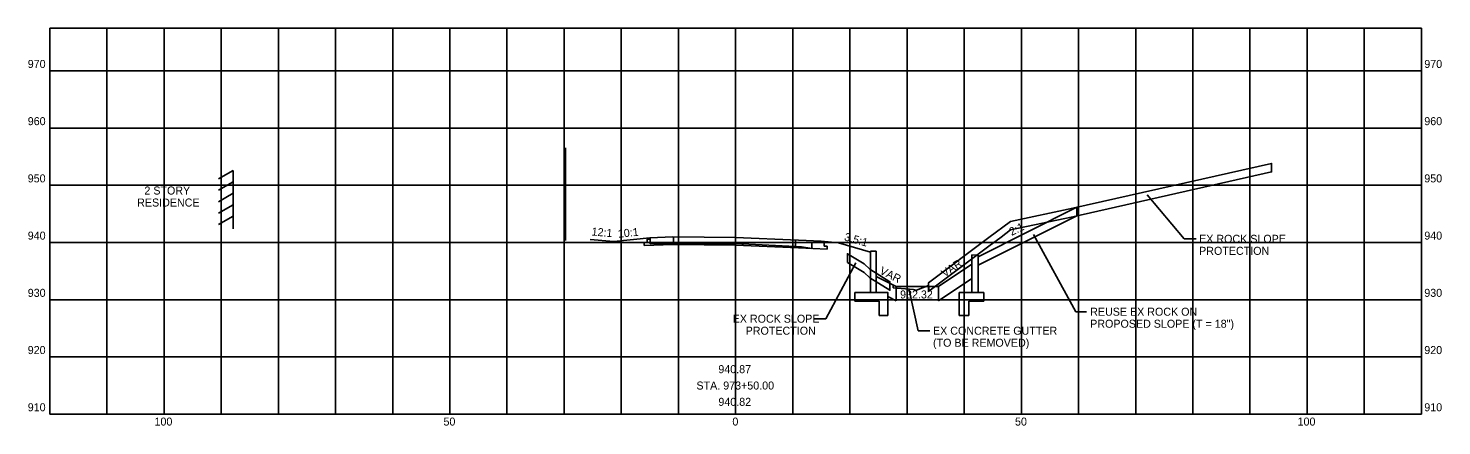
# Model space of a CAD drawing. Extents: x -124 to 124, y 908 to 977.
import ezdxf

# ---------------------------------------------------------------- set-up
doc = ezdxf.new("R2010")
doc.units = 0
for name, color, linetype in [('BD_X_Building', 7, 'Continuous'), ('GT_Project_Soil_Boring', 7, 'Continuous'), ('RD_X_Misc_Items', 7, 'Continuous'), ('SH_Major_Grid_Line', 7, 'Continuous'), ('SH_Text', 7, 'Continuous'), ('SN_X_Public', 7, 'Continuous'), ('SV_P_Aerial_Targets', 7, 'Continuous'), ('SV_X_Control_Cells_Found', 7, 'Continuous'), ('SV_X_Mon_Cells_Found', 7, 'Continuous'), ('SV_X_Random_Point', 7, 'Continuous'), ('UT_X_Gas_Cells', 7, 'Continuous'), ('UT_X_Sanitary_Cells', 7, 'Continuous'), ('UT_X_Water_Cells', 7, 'Continuous')]:
    doc.layers.add(name, color=color, linetype=linetype)

msp = doc.modelspace()

# ---------------------------------------------------------------- linework, layer by layer
at = {"layer": 'BD_X_Building'}
for p, q in [((59.73, 946.16), (42.45, 937.52)), ((59.73, 946.16), (59.73, 944.66)), ((59.73, 944.66), (42.45, 936.02)), ((35.52, 932.32), (41.34, 936.2)), ((28.07, 932.32), (24.62, 934.03)), ((35.52, 929.82), (41.34, 933.7)), ((28.07, 929.82), (26.62, 930.54)), ((28.07, 932.32), (28.07, 929.82)), ((35.52, 932.32), (35.52, 929.82))]:
    msp.add_line(p, q, dxfattribs=at)
for points in [[(42.45, 936.02), (59.73, 944.66), (59.73, 946.16), (42.45, 937.52), (42.45, 936.02)], [(35.52, 929.82), (41.34, 933.7), (41.34, 936.2), (35.52, 932.32), (35.52, 929.82)], [(28.07, 929.82), (28.07, 932.32), (24.62, 934.03), (24.62, 931.26), (26.62, 931.26), (26.62, 930.54)]]:
    msp.add_lwpolyline(points, close=True, dxfattribs=at)
at = {"layer": 'GT_Project_Soil_Boring'}
for p, q in [((-87.91, 952.6), (-90.49, 951.13)), ((-87.91, 942.37), (-87.91, 952.6)), ((-87.91, 950.6), (-90.49, 949.13)), ((-87.91, 948.6), (-90.49, 947.13)), ((-87.91, 946.6), (-90.49, 945.13)), ((-87.91, 944.6), (-90.49, 943.13))]:
    msp.add_line(p, q, dxfattribs=at)
at = {"layer": 'RD_X_Misc_Items'}
for p, q in [((-21.32, 940.2), (-25.46, 940.54)), ((-15, 940.83), (-21.32, 940.2)), ((15, 940.22), (18, 939.92)), ((18, 939.92), (23.62, 938.32)), ((28.07, 932.32), (35.52, 932.32))]:
    msp.add_line(p, q, dxfattribs=at)
at = {"layer": 'SH_Major_Grid_Line'}
for p, q in [((-120, 977.43), (120, 977.43)), ((-120, 910), (-120, 977.43)), ((-110, 910), (-110, 977.43)), ((-100, 910), (-100, 977.43)), ((-90, 910), (-90, 977.43)), ((-80, 910), (-80, 977.43)), ((-70, 910), (-70, 977.43)), ((-60, 910), (-60, 977.43)), ((-50, 910), (-50, 977.43)), ((-40, 910), (-40, 977.43)), ((-30, 910), (-30, 977.43)), ((-20, 910), (-20, 977.43)), ((-10, 910), (-10, 977.43)), ((0, 910), (0, 977.43)), ((10, 910), (10, 977.43)), ((20, 910), (20, 977.43)), ((30, 910), (30, 977.43)), ((40, 910), (40, 977.43)), ((50, 910), (50, 977.43)), ((60, 910), (60, 977.43)), ((70, 910), (70, 977.43)), ((80, 910), (80, 977.43)), ((90, 910), (90, 977.43)), ((100, 910), (100, 977.43)), ((110, 910), (110, 977.43)), ((120, 910), (120, 977.43)), ((-120, 970), (120, 970)), ((-120, 960), (120, 960)), ((-120, 950), (120, 950)), ((-120, 940), (120, 940)), ((-120, 930), (120, 930)), ((-120, 920), (120, 920)), ((-120, 910), (120, 910))]:
    msp.add_line(p, q, dxfattribs=at)
at = {"layer": 'SN_X_Public'}
for p, q in [((-14.96, 939.77), (-14.96, 940.77)), ((-10.89, 939.85), (-10.89, 940.85)), ((10.48, 939.3), (10.48, 940.3)), ((13.32, 938.95), (13.32, 939.95))]:
    msp.add_line(p, q, dxfattribs=at)
msp.add_lwpolyline([(-14.96, 939.77), (-12.52, 939.81), (-10.89, 939.85), (-8.36, 939.85), (-0.19, 939.83), (2.3, 939.71), (10.48, 939.3), (11.51, 939.22), (13.32, 938.95)], dxfattribs=at)
at = {"layer": 'SV_P_Aerial_Targets'}
for p, q in [((78.51, 940.64), (72.03, 948.35)), ((80.56, 940.64), (78.51, 940.64)), ((15.81, 926.68), (21.06, 936.43)), ((31.95, 924.58), (30.32, 931.95)), ((13.76, 926.68), (15.81, 926.68)), ((33.99, 924.58), (31.95, 924.58))]:
    msp.add_line(p, q, dxfattribs=at)
at = {"layer": 'SV_X_Control_Cells_Found'}
for p, q in [((-15.5, 939.98), (-16, 939.96)), ((-16, 939.96), (-16, 939.46)), ((-15, 940.58), (-15.5, 940.56)), ((-15.5, 940.56), (-15.5, 939.98)), ((-11, 940.99), (-15, 940.83)), ((-15, 940.83), (-15, 940.58)), ((0, 940.87), (-11, 940.99)), ((0, 940.87), (11, 940.4)), ((11, 940.4), (15, 940.22)), ((15, 940.22), (15, 939.97)), ((15, 939.97), (15.5, 939.95)), ((15.5, 939.95), (15.5, 939.37)), ((-11, 939.66), (-16, 939.46)), ((0, 939.54), (-11, 939.66)), ((0, 939.54), (11, 939.06)), ((11, 939.06), (16, 938.85)), ((15.5, 939.37), (16, 939.35)), ((16, 939.35), (16, 938.85))]:
    msp.add_line(p, q, dxfattribs=at)
at = {"layer": 'SV_X_Mon_Cells_Found'}
for p, q in [((59.54, 927.9), (52.12, 941.37)), ((61.42, 927.9), (59.54, 927.9))]:
    msp.add_line(p, q, dxfattribs=at)
at = {"layer": 'SV_X_Random_Point'}
for p, q in [((93.79, 952.83), (93.79, 953.83)), ((93.79, 953.83), (93.79, 952.33)), ((19.57, 937.02), (19.57, 938.02)), ((19.57, 938.02), (19.57, 936.52)), ((27, 932.14), (27, 933.14)), ((27, 933.14), (27, 931.64)), ((33.78, 931.97), (33.78, 932.97)), ((33.78, 932.97), (33.78, 931.47))]:
    msp.add_line(p, q, dxfattribs=at)
for points in [[(33.78, 932.97), (33.79, 931.47), (44.29, 939.35), (46.46, 940.95), (48.07, 942.19), (58.99, 944.49), (93.79, 952.33), (93.79, 953.83), (58.99, 945.99), (48.07, 943.69), (44.29, 940.85), (33.78, 932.97), (33.79, 931.47)], [(19.57, 936.52), (22.5, 934.78), (23.49, 933.83), (27, 931.64), (27, 933.14), (23.48, 935.34), (22.5, 936.28), (19.57, 938.03), (19.57, 936.52)]]:
    msp.add_lwpolyline(points, close=True, dxfattribs=at)
for points in [[(33.79, 931.47), (44.29, 939.35), (46.46, 940.95), (48.07, 942.19), (58.99, 944.49), (93.79, 952.33)], [(19.57, 936.52), (22.5, 934.78), (23.49, 933.83), (27, 931.64)]]:
    msp.add_lwpolyline(points, dxfattribs=at)
at = {"layer": 'UT_X_Gas_Cells'}
for p, q in [((27.59, 932.09), (27.59, 932.59)), ((33.78, 932.47), (33.78, 932.97))]:
    msp.add_line(p, q, dxfattribs=at)
msp.add_lwpolyline([(27.59, 932.09), (31.11, 931.78), (31.64, 931.67), (33.78, 932.47)], dxfattribs=at)
at = {"layer": 'UT_X_Sanitary_Cells'}
for p, q in [((70, 948.47), (70, 964.66)), ((-29.75, 940.33), (-29.75, 956.52))]:
    msp.add_line(p, q, dxfattribs=at)
at = {"layer": 'UT_X_Water_Cells'}
for p, q in [((23.62, 931.26), (23.62, 938.47)), ((23.62, 938.47), (24.62, 938.47)), ((24.62, 931.26), (24.62, 938.47)), ((41.34, 931.26), (41.34, 937.82)), ((41.34, 937.82), (42.45, 937.77)), ((42.45, 931.26), (42.45, 937.77)), ((20.87, 929.76), (20.87, 931.26)), ((20.87, 931.26), (26.62, 931.26)), ((26.62, 927.26), (26.62, 931.26)), ((39.12, 927.26), (39.12, 931.26)), ((39.12, 931.26), (43.42, 931.26)), ((43.42, 929.76), (43.42, 931.26)), ((20.87, 929.76), (25.12, 929.76)), ((25.12, 927.26), (25.12, 929.76)), ((40.79, 927.26), (40.79, 929.76)), ((40.79, 929.76), (43.42, 929.76)), ((25.12, 927.26), (26.62, 927.26)), ((39.12, 927.26), (40.79, 927.26))]:
    msp.add_line(p, q, dxfattribs=at)

# ---------------------------------------------------------------- texts
at = {"layer": 'SH_Text'}
for s, p in [('970', (-123.85, 970.5)), ('970', (120.5, 970.5)), ('960', (-123.85, 960.5)), ('960', (120.5, 960.5)), ('950', (-123.85, 950.5)), ('950', (120.5, 950.5)), ('940', (-123.85, 940.5)), ('940', (120.5, 940.5)), ('930', (-123.85, 930.5)), ('930', (120.5, 930.5)), ('920', (-123.85, 920.5)), ('920', (120.5, 920.5)), ('STA. 973+50.00', (-6.85, 914.3)), ('910', (-123.85, 910.5)), ('910', (120.5, 910.5)), ('100', (-101.67, 908)), ('50', (-51.11, 908)), ('0', (-0.56, 908)), ('50', (48.89, 908)), ('100', (98.33, 908))]:
    msp.add_text(s, height=1.4, dxfattribs=at).set_placement(p)
at = {"layer": 'SV_P_Aerial_Targets'}
for s, p in [('2 STORY', (-103.44, 948.38)), ('RESIDENCE', (-104.71, 946.28)), ('EX ROCK SLOPE', (81.1, 939.94)), ('PROTECTION', (81.1, 937.84)), ('EX ROCK SLOPE', (-0.51, 925.98)), ('PROTECTION', (1.76, 923.88)), ('EX CONCRETE GUTTER', (34.54, 923.88)), ('(TO BE REMOVED)', (34.54, 921.78)), ('940.82', (-3.01, 911.45))]:
    msp.add_text(s, height=1.4, dxfattribs=at).set_placement(p)
at = {"layer": 'SV_X_Mon_Cells_Found'}
for s, rotation, p in [('12:1', 355.2364, (-25.24, 941.23)), ('10:1', 5.7106, (-20.53, 940.82)), ('2:1', 26.5651, (48.3, 941.14)), ('3.5:1', 344.0546, (18.9, 940.4)), ('VAR', 333.6346, (25.07, 934.59)), ('VAR', 33.6901, (36.57, 933.86))]:
    msp.add_text(s, height=1.4, rotation=rotation, dxfattribs=at).set_placement(p)
for s, p in [('932.32', (28.78, 930.22)), ('REUSE EX ROCK ON', (62.04, 927.2)), ('PROPOSED SLOPE (T = 18")', (62.04, 925.1)), ('940.87', (-3.02, 917.16))]:
    msp.add_text(s, height=1.4, dxfattribs=at).set_placement(p)

doc.saveas('drawing.dxf')
